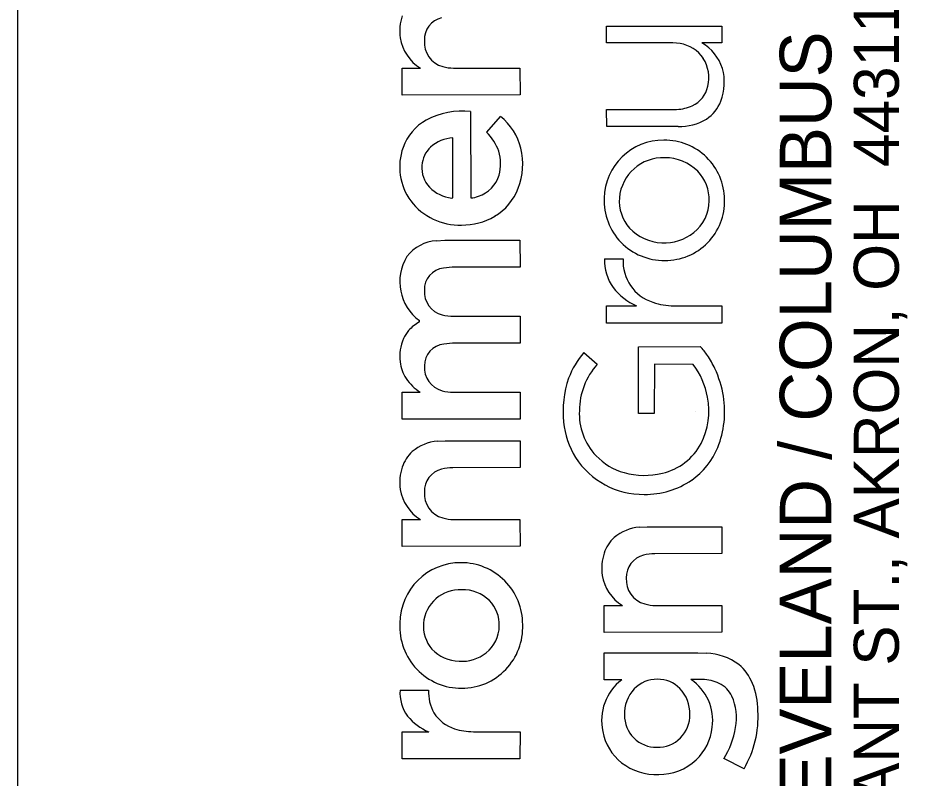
# Model space of a CAD drawing. Extents: x 0 to 34, y 0 to 22.
# Drawn here: x 32 to 32.984, y 3.594 to 4.436 of the extents above; entities that cross this region are included whole.
import ezdxf

# ---------------------------------------------------------------- set-up
doc = ezdxf.new("R2010")
doc.units = 0
doc.layers.add('SH_Border', color=7, linetype='Continuous')
doc.layers.add('SH_Data', color=7, linetype='Continuous')

msp = doc.modelspace()

# ---------------------------------------------------------------- linework, layer by layer
at = {"layer": 'SH_Border'}
msp.add_line((32, 0.5), (32, 21.5), dxfattribs=at)
at = {"layer": 'SH_Data'}
for p, q in [((32.65152, 4.40801), (32.65153, 4.42672)), ((32.65153, 4.42672), (32.7791, 4.42664)), ((32.7791, 4.42664), (32.77908, 4.40796)), ((32.7249, 4.40796), (32.65152, 4.40801)), ((32.7328, 4.40727), (32.7249, 4.40796)), ((32.77908, 4.40796), (32.75689, 4.40796)), ((32.42542, 4.38016), (32.44552, 4.38021)), ((32.42542, 4.35035), (32.42542, 4.38016)), ((32.48222, 4.38021), (32.55569, 4.38021)), ((32.55569, 4.38021), (32.55571, 4.35045)), ((32.55571, 4.35045), (32.42542, 4.35035)), ((32.50108, 4.33209), (32.50118, 4.23657)), ((32.65154, 4.33443), (32.72905, 4.3345)), ((32.65165, 4.31543), (32.65154, 4.33443)), ((32.51882, 4.30927), (32.53422, 4.32662)), ((32.73073, 4.31543), (32.65165, 4.31543)), ((32.48144, 4.23644), (32.48144, 4.30296)), ((32.48016, 4.23628), (32.48144, 4.23644)), ((32.46329, 4.18915), (32.47259, 4.18968)), ((32.47259, 4.18968), (32.55557, 4.18968)), ((32.55557, 4.18968), (32.55571, 4.15982)), ((32.64932, 4.16907), (32.66978, 4.16907)), ((32.48058, 4.15981), (32.47102, 4.15881)), ((32.55571, 4.15982), (32.48058, 4.15981)), ((32.65152, 4.11699), (32.68476, 4.117)), ((32.65152, 4.098), (32.65152, 4.11699)), ((32.72605, 4.11703), (32.7791, 4.11696)), ((32.7791, 4.11696), (32.77903, 4.098)), ((32.48218, 4.10553), (32.55571, 4.10548)), ((32.55571, 4.10548), (32.55571, 4.07568)), ((32.44443, 4.09922), (32.44455, 4.10072)), ((32.77903, 4.098), (32.65152, 4.098)), ((32.4809, 4.07567), (32.47143, 4.07474)), ((32.55571, 4.07568), (32.4809, 4.07567)), ((32.62636, 4.06548), (32.64114, 4.05241)), ((32.6868, 4.07185), (32.75516, 4.07192)), ((32.6868, 3.99778), (32.6868, 4.07185)), ((32.70448, 4.05241), (32.70432, 3.99775)), ((32.74737, 4.05227), (32.70448, 4.05241)), ((32.42542, 3.99152), (32.42545, 4.02138)), ((32.42545, 4.02138), (32.44515, 4.02138)), ((32.48206, 4.02138), (32.55571, 4.02136)), ((32.55571, 4.02136), (32.55571, 3.99156)), ((32.70432, 3.99775), (32.6868, 3.99778)), ((32.75, 4), (32.75, 4)), ((32.55571, 3.99156), (32.42542, 3.99152)), ((32.46439, 3.96736), (32.47289, 3.96783)), ((32.47289, 3.96783), (32.55571, 3.96783)), ((32.55571, 3.96783), (32.55571, 3.93804)), ((32.55571, 3.93804), (32.4814, 3.93796)), ((32.42542, 3.88066), (32.44552, 3.88071)), ((32.42542, 3.85086), (32.42542, 3.88066)), ((32.48222, 3.88071), (32.55569, 3.88071)), ((32.55569, 3.88071), (32.55571, 3.85096)), ((32.68784, 3.8722), (32.69634, 3.87266)), ((32.69634, 3.87266), (32.77916, 3.87266)), ((32.77916, 3.87266), (32.77917, 3.84287)), ((32.55571, 3.85096), (32.42542, 3.85086)), ((32.77917, 3.84287), (32.70485, 3.8428)), ((32.64888, 3.7855), (32.66897, 3.78555)), ((32.64888, 3.75569), (32.64888, 3.7855)), ((32.70568, 3.78555), (32.77915, 3.78555)), ((32.77915, 3.78555), (32.77917, 3.75579)), ((32.77917, 3.75579), (32.64888, 3.75569)), ((32.6489, 3.70336), (32.64889, 3.73322)), ((32.64889, 3.73322), (32.75236, 3.73322)), ((32.75236, 3.73322), (32.76191, 3.73285)), ((32.66836, 3.70336), (32.6489, 3.70336)), ((32.75763, 3.70356), (32.74487, 3.70361)), ((32.42299, 3.69193), (32.45454, 3.69193)), ((32.42542, 3.64577), (32.45473, 3.64579)), ((32.42542, 3.61593), (32.42542, 3.64577)), ((32.50413, 3.64581), (32.55571, 3.64573)), ((32.55571, 3.64573), (32.55565, 3.61593)), ((32.55565, 3.61593), (32.42542, 3.61593)), ((32.8036, 3.60491), (32.7812, 3.61598))]:
    msp.add_line(p, q, dxfattribs=at)
for points in [[(32.7328, 4.40727), (32.7249, 4.40796), (32.65152, 4.40801), (32.65153, 4.42672), (32.7791, 4.42664), (32.77908, 4.40796), (32.75689, 4.40796)], [(32.42542, 4.35035), (32.42542, 4.38016), (32.44552, 4.38021)], [(32.48222, 4.38021), (32.55569, 4.38021), (32.55571, 4.35045), (32.42542, 4.35035)], [(32.50108, 4.33209), (32.50118, 4.23657)], [(32.73073, 4.31543), (32.65165, 4.31543), (32.65154, 4.33443), (32.72905, 4.3345)], [(32.51882, 4.30927), (32.53422, 4.32662)], [(32.48016, 4.23628), (32.48144, 4.23644), (32.48144, 4.30296)], [(32.46329, 4.18915), (32.47259, 4.18968), (32.55557, 4.18968), (32.55571, 4.15982), (32.48058, 4.15981), (32.47102, 4.15881)], [(32.64932, 4.16907), (32.66978, 4.16907)], [(32.72605, 4.11703), (32.7791, 4.11696), (32.77903, 4.098), (32.65152, 4.098)], [(32.65152, 4.098), (32.65152, 4.11699), (32.68476, 4.117)], [(32.48218, 4.10553), (32.55571, 4.10548), (32.55571, 4.07568), (32.4809, 4.07567), (32.47143, 4.07474)], [(32.44443, 4.09922), (32.44455, 4.10072)], [(32.62636, 4.06548), (32.64114, 4.05241)], [(32.74737, 4.05227), (32.70448, 4.05241), (32.70432, 3.99775), (32.6868, 3.99778), (32.6868, 4.07185), (32.75516, 4.07192)], [(32.42542, 3.99152), (32.42545, 4.02138), (32.44515, 4.02138)], [(32.48206, 4.02138), (32.55571, 4.02136), (32.55571, 3.99156), (32.42542, 3.99152)], [(32.46439, 3.96736), (32.47289, 3.96783), (32.55571, 3.96783), (32.55571, 3.93804), (32.4814, 3.93796)], [(32.42542, 3.85086), (32.42542, 3.88066), (32.44552, 3.88071)], [(32.48222, 3.88071), (32.55569, 3.88071), (32.55571, 3.85096), (32.42542, 3.85086)], [(32.68784, 3.8722), (32.69634, 3.87266), (32.77916, 3.87266), (32.77917, 3.84287), (32.70485, 3.8428)], [(32.64888, 3.75569), (32.64888, 3.7855), (32.66897, 3.78555)], [(32.70568, 3.78555), (32.77915, 3.78555), (32.77917, 3.75579), (32.64888, 3.75569)], [(32.66836, 3.70336), (32.6489, 3.70336), (32.64889, 3.73322), (32.75236, 3.73322), (32.76191, 3.73285)], [(32.75763, 3.70356), (32.74487, 3.70361)], [(32.42299, 3.69193), (32.45454, 3.69193)], [(32.50413, 3.64581), (32.55571, 3.64573), (32.55565, 3.61593), (32.42542, 3.61593)], [(32.42542, 3.61593), (32.42542, 3.64577), (32.45473, 3.64579)], [(32.8036, 3.60491), (32.7812, 3.61598)]]:
    msp.add_lwpolyline(points, dxfattribs=at)
for centre, radius, start, end in [((32.47872, 4.42108), 0.05602, 162.27398, 187.79173), ((32.47872, 4.42108), 0.05602, 162.27398, 187.79173), ((32.47482, 4.41155), 0.02498, 103.68683, 182.21395), ((32.47482, 4.41155), 0.02498, 103.68683, 182.21395), ((32.47027, 4.4209), 0.04763, 188.96462, 238.69865), ((32.47027, 4.4209), 0.04763, 188.96462, 238.69865), ((32.47735, 4.40846), 0.02757, 175.58441, 255.13816), ((32.47735, 4.40846), 0.02757, 175.58441, 255.13816), ((32.72711, 4.36998), 0.03772, 33.50082, 81.32954), ((32.72711, 4.36998), 0.03772, 33.50082, 81.32954), ((32.73239, 4.36485), 0.04959, 17.62209, 60.38974), ((32.73239, 4.36485), 0.04959, 17.62209, 60.38974), ((32.72414, 4.3695), 0.04048, 346.56179, 31.75389), ((32.72414, 4.3695), 0.04048, 346.56179, 31.75389), ((32.48183, 4.42235), 0.04215, 254.08913, 270.52838), ((32.48183, 4.42235), 0.04215, 254.08913, 270.52838), ((32.72343, 4.36415), 0.05838, 339.16197, 15.61485), ((32.72343, 4.36415), 0.05838, 339.16197, 15.61485), ((32.73371, 4.36616), 0.03042, 294.63214, 348.48625), ((32.73371, 4.36616), 0.03042, 294.63214, 348.48625), ((32.739, 4.35901), 0.04201, 303.10391, 338.15613), ((32.739, 4.35901), 0.04201, 303.10391, 338.15613), ((32.49176, 4.24874), 0.08387, 83.62118, 118.28448), ((32.49176, 4.24874), 0.08387, 83.62118, 118.28448), ((32.72747, 4.38081), 0.04633, 271.95199, 294.08943), ((32.72747, 4.38081), 0.04633, 271.95199, 294.08943), ((32.47894, 4.27368), 0.05583, 118.82935, 160.62242), ((32.47894, 4.27368), 0.05583, 118.82935, 160.62242), ((32.49399, 4.2763), 0.06443, 13.53275, 51.36266), ((32.49399, 4.2763), 0.06443, 13.53275, 51.36266), ((32.7321, 4.37256), 0.05715, 268.62699, 301.47779), ((32.7321, 4.37256), 0.05715, 268.62699, 301.47779), ((32.4844, 4.26071), 0.04236, 94.01311, 130.88062), ((32.4844, 4.26071), 0.04236, 94.01311, 130.88062), ((32.48033, 4.27018), 0.05485, 19.0387, 45.44322), ((32.48033, 4.27018), 0.05485, 19.0387, 45.44322), ((32.48697, 4.27074), 0.06438, 160.52138, 215.78155), ((32.48697, 4.27074), 0.06438, 160.52138, 215.78155), ((32.47703, 4.2709), 0.02985, 132.98553, 177.1802), ((32.47703, 4.2709), 0.02985, 132.98553, 177.1802), ((32.48289, 4.27384), 0.0758, 339.35431, 13.37708), ((32.48289, 4.27384), 0.0758, 339.35431, 13.37708), ((32.71435, 4.23484), 0.06552, 89.48213, 178.77752), ((32.71435, 4.23484), 0.06552, 89.48213, 178.77752), ((32.71582, 4.23414), 0.06623, 0.42265, 90.7613), ((32.71582, 4.23414), 0.06623, 0.42265, 90.7613), ((32.48724, 4.27433), 0.04701, 344.60723, 17.00675), ((32.48724, 4.27433), 0.04701, 344.60723, 17.00675), ((32.47824, 4.26966), 0.03114, 175.00138, 223.2876), ((32.47824, 4.26966), 0.03114, 175.00138, 223.2876), ((32.71397, 4.23244), 0.04846, 87.68827, 175.01696), ((32.71397, 4.23244), 0.04846, 87.68827, 175.01696), ((32.71659, 4.23036), 0.05052, 44.91202, 90.75914), ((32.71659, 4.23036), 0.05052, 44.91202, 90.75914), ((32.49895, 4.27177), 0.03504, 288.01084, 343.55364), ((32.49895, 4.27177), 0.03504, 288.01084, 343.55364), ((32.71955, 4.23452), 0.04549, 358.32279, 43.83486), ((32.71955, 4.23452), 0.04549, 358.32279, 43.83486), ((32.48546, 4.27826), 0.04232, 225.06454, 262.79701), ((32.48546, 4.27826), 0.04232, 225.06454, 262.79701), ((32.49548, 4.26982), 0.0626, 300.94393, 338.73223), ((32.49548, 4.26982), 0.0626, 300.94393, 338.73223), ((32.48908, 4.27516), 0.06872, 217.74341, 271.65606), ((32.48908, 4.27516), 0.06872, 217.74341, 271.65606), ((32.50129, 4.25678), 0.02021, 269.70042, 294.87295), ((32.50129, 4.25678), 0.02021, 269.70042, 294.87295), ((32.71483, 4.2334), 0.06606, 177.53728, 270.94524), ((32.71483, 4.2334), 0.06606, 177.53728, 270.94524), ((32.71085, 4.23311), 0.0453, 175.51467, 221.42047), ((32.71085, 4.23311), 0.0453, 175.51467, 221.42047), ((32.71671, 4.23271), 0.06536, 269.30834, 1.67905), ((32.71671, 4.23271), 0.06536, 269.30834, 1.67905), ((32.71931, 4.23374), 0.04572, 308.90382, 359.30947), ((32.71931, 4.23374), 0.04572, 308.90382, 359.30947), ((32.49204, 4.27702), 0.07055, 269.20529, 300.33566), ((32.49204, 4.27702), 0.07055, 269.20529, 300.33566), ((32.71399, 4.23734), 0.05046, 222.66255, 268.37331), ((32.71399, 4.23734), 0.05046, 222.66255, 268.37331), ((32.71567, 4.23859), 0.05178, 266.55312, 308.67253), ((32.71567, 4.23859), 0.05178, 266.55312, 308.67253), ((32.46638, 4.14404), 0.04521, 93.91118, 142.30723), ((32.46638, 4.14404), 0.04521, 93.91118, 142.30723), ((32.47585, 4.14373), 0.05319, 148.28793, 233.9556), ((32.47585, 4.14373), 0.05319, 148.28793, 233.9556), ((32.69878, 4.16662), 0.04952, 177.16211, 216.28024), ((32.69878, 4.16662), 0.04952, 177.16211, 216.28024), ((32.71735, 4.16638), 0.04764, 176.76988, 252.15044), ((32.71735, 4.16638), 0.04764, 176.76988, 252.15044), ((32.47384, 4.13499), 0.02399, 96.75763, 181.6251), ((32.47384, 4.13499), 0.02399, 96.75763, 181.6251), ((32.47577, 4.13241), 0.02597, 175.81573, 256.16716), ((32.47577, 4.13241), 0.02597, 175.81573, 256.16716), ((32.70975, 4.17555), 0.06366, 216.91526, 246.88619), ((32.70975, 4.17555), 0.06366, 216.91526, 246.88619), ((32.7269, 4.19175), 0.07473, 251.13884, 269.34694), ((32.7269, 4.19175), 0.07473, 251.13884, 269.34694), ((32.4817, 4.15053), 0.04501, 254.34629, 270.61033), ((32.4817, 4.15053), 0.04501, 254.34629, 270.61033), ((32.4638, 4.06267), 0.04137, 117.91625, 139.24296), ((32.4638, 4.06267), 0.04137, 117.91625, 139.24296), ((32.46194, 4.06452), 0.03875, 139.52447, 154.84698), ((32.46194, 4.06452), 0.03875, 139.52447, 154.84698), ((32.47144, 4.0612), 0.04877, 156.06382, 187.3493), ((32.47144, 4.0612), 0.04877, 156.06382, 187.3493), ((32.47421, 4.05056), 0.02434, 96.5532, 179.94902), ((32.47421, 4.05056), 0.02434, 96.5532, 179.94902), ((32.70163, 4.00187), 0.09855, 139.79476, 159.13696), ((32.70163, 4.00187), 0.09855, 139.79476, 159.13696), ((32.72498, 4.03937), 0.04438, 30.98913, 47.16099), ((32.72498, 4.03937), 0.04438, 30.98913, 47.16099), ((32.46461, 4.05974), 0.04181, 186.5579, 213.38846), ((32.46461, 4.05974), 0.04181, 186.5579, 213.38846), ((32.67091, 4.00018), 0.11106, 25.30315, 33.96179), ((32.67091, 4.00018), 0.11106, 25.30315, 33.96179), ((32.47608, 4.04863), 0.02628, 175.722, 255.78627), ((32.47608, 4.04863), 0.02628, 175.722, 255.78627), ((32.69899, 4.00079), 0.07753, 138.25804, 179.70064), ((32.69899, 4.00079), 0.07753, 138.25804, 179.70064), ((32.67889, 4.00099), 0.08556, 10.07509, 36.83189), ((32.67889, 4.00099), 0.08556, 10.07509, 36.83189), ((32.6704, 3.99987), 0.11166, 8.80339, 25.33484), ((32.6704, 3.99987), 0.11166, 8.80339, 25.33484), ((32.47886, 4.07078), 0.0598, 214.70433, 235.68724), ((32.47886, 4.07078), 0.0598, 214.70433, 235.68724), ((32.7187, 3.99968), 0.11536, 161.14379, 185.62812), ((32.7187, 3.99968), 0.11536, 161.14379, 185.62812), ((32.48195, 4.06518), 0.0438, 253.66719, 270.14979), ((32.48195, 4.06518), 0.0438, 253.66719, 270.14979), ((32.68425, 4.00057), 0.08036, 333.46689, 11.03668), ((32.68425, 4.00057), 0.08036, 333.46689, 11.03668), ((32.67564, 3.99977), 0.10649, 338.28866, 9.28548), ((32.67564, 3.99977), 0.10649, 338.28866, 9.28548), ((32.68811, 3.99732), 0.06676, 176.66577, 223.6912), ((32.68811, 3.99732), 0.06676, 176.66577, 223.6912), ((32.69336, 3.99699), 0.08987, 185.50773, 212.01294), ((32.69336, 3.99699), 0.08987, 185.50773, 212.01294), ((32.46871, 3.91767), 0.04988, 94.97056, 130.22484), ((32.46871, 3.91767), 0.04988, 94.97056, 130.22484), ((32.69868, 3.99547), 0.0652, 282.88151, 331.81475), ((32.69868, 3.99547), 0.0652, 282.88151, 331.81475), ((32.69835, 3.99168), 0.08241, 305.03061, 337.67573), ((32.69835, 3.99168), 0.08241, 305.03061, 337.67573), ((32.46348, 3.92602), 0.04016, 132.22383, 161.68229), ((32.46348, 3.92602), 0.04016, 132.22383, 161.68229), ((32.69211, 3.99748), 0.08908, 212.70222, 270.71399), ((32.69211, 3.99748), 0.08908, 212.70222, 270.71399), ((32.69045, 4.00011), 0.07039, 224.02147, 253.88), ((32.69045, 4.00011), 0.07039, 224.02147, 253.88), ((32.47872, 3.92158), 0.05602, 162.27398, 187.79173), ((32.47872, 3.92158), 0.05602, 162.27398, 187.79173), ((32.48108, 3.89196), 0.04601, 89.60515, 105.33026), ((32.48108, 3.89196), 0.04601, 89.60515, 105.33026), ((32.47482, 3.91206), 0.02498, 103.68683, 182.21395), ((32.47482, 3.91206), 0.02498, 103.68683, 182.21395), ((32.69318, 4.01254), 0.08309, 254.45353, 283.9512), ((32.69318, 4.01254), 0.08309, 254.45353, 283.9512), ((32.69429, 3.99979), 0.09138, 269.3273, 304.19632), ((32.69429, 3.99979), 0.09138, 269.3273, 304.19632), ((32.47027, 3.92141), 0.04763, 188.96462, 238.69865), ((32.47027, 3.92141), 0.04763, 188.96462, 238.69865), ((32.47735, 3.90897), 0.02757, 175.58441, 255.13816), ((32.47735, 3.90897), 0.02757, 175.58441, 255.13816), ((32.48183, 3.92286), 0.04215, 254.08913, 270.52838), ((32.48183, 3.92286), 0.04215, 254.08913, 270.52838), ((32.69216, 3.82251), 0.04988, 94.97056, 130.22484), ((32.69216, 3.82251), 0.04988, 94.97056, 130.22484), ((32.68694, 3.83085), 0.04016, 132.22383, 161.68229), ((32.68694, 3.83085), 0.04016, 132.22383, 161.68229), ((32.70217, 3.82642), 0.05602, 162.27398, 187.79173), ((32.70217, 3.82642), 0.05602, 162.27398, 187.79173), ((32.69828, 3.81689), 0.02498, 103.68683, 182.21395), ((32.69828, 3.81689), 0.02498, 103.68683, 182.21395), ((32.70453, 3.79679), 0.04601, 89.60515, 105.33026), ((32.70453, 3.79679), 0.04601, 89.60515, 105.33026), ((32.49014, 3.76543), 0.0674, 89.84756, 179.64047), ((32.49014, 3.76543), 0.0674, 89.84756, 179.64047), ((32.49057, 3.76474), 0.0681, 359.54009, 90.21138), ((32.49057, 3.76474), 0.0681, 359.54009, 90.21138), ((32.69372, 3.82624), 0.04763, 188.96462, 238.69865), ((32.69372, 3.82624), 0.04763, 188.96462, 238.69865), ((32.7008, 3.81381), 0.02757, 175.58441, 255.13816), ((32.7008, 3.81381), 0.02757, 175.58441, 255.13816), ((32.48923, 3.76263), 0.0404, 87.04809, 175.57259), ((32.48923, 3.76263), 0.0404, 87.04809, 175.57259), ((32.49204, 3.75999), 0.04299, 45.84264, 90.98008), ((32.49204, 3.75999), 0.04299, 45.84264, 90.98008), ((32.49458, 3.76421), 0.03821, 357.88569, 44.15902), ((32.49458, 3.76421), 0.03821, 357.88569, 44.15902), ((32.70529, 3.82769), 0.04215, 254.08913, 270.52838), ((32.70529, 3.82769), 0.04215, 254.08913, 270.52838), ((32.49083, 3.76209), 0.06819, 176.8344, 270.40384), ((32.49083, 3.76209), 0.06819, 176.8344, 270.40384), ((32.48729, 3.7625), 0.03848, 175.15378, 221.14706), ((32.48729, 3.7625), 0.03848, 175.15378, 221.14706), ((32.49123, 3.76139), 0.06749, 270.06243, 2.37759), ((32.49123, 3.76139), 0.06749, 270.06243, 2.37759), ((32.49446, 3.76318), 0.0383, 308.28936, 359.43468), ((32.49446, 3.76318), 0.0383, 308.28936, 359.43468), ((32.48919, 3.76607), 0.04228, 223.09994, 268.80895), ((32.48919, 3.76607), 0.04228, 223.09994, 268.80895), ((32.49096, 3.7679), 0.04418, 266.56515, 308.06078), ((32.49096, 3.7679), 0.04418, 266.56515, 308.06078), ((32.75907, 3.66789), 0.06503, 53.40344, 87.49062), ((32.75907, 3.66789), 0.06503, 53.40344, 87.49062), ((32.76517, 3.68039), 0.05141, 21.60748, 50.5577), ((32.76517, 3.68039), 0.05141, 21.60748, 50.5577), ((32.70292, 3.65813), 0.05692, 127.37482, 192.22468), ((32.70292, 3.65813), 0.05692, 127.37482, 192.22468), ((32.70693, 3.66927), 0.0346, 88.47302, 136.42562), ((32.70693, 3.66927), 0.0346, 88.47302, 136.42562), ((32.70814, 3.66963), 0.03424, 44.27195, 90.47623), ((32.70814, 3.66963), 0.03424, 44.27195, 90.47623), ((32.71421, 3.65829), 0.05472, 352.1125, 55.92295), ((32.71421, 3.65829), 0.05472, 352.1125, 55.92295), ((32.75666, 3.65725), 0.04633, 65.01687, 88.8011), ((32.75666, 3.65725), 0.04633, 65.01687, 88.8011), ((32.46616, 3.68882), 0.04329, 175.87313, 216.34747), ((32.46616, 3.68882), 0.04329, 175.87313, 216.34747), ((32.50087, 3.68948), 0.04639, 176.9688, 209.60636), ((32.50087, 3.68948), 0.04639, 176.9688, 209.60636), ((32.71141, 3.66602), 0.0401, 137.46739, 182.33237), ((32.71141, 3.66602), 0.0401, 137.46739, 182.33237), ((32.70368, 3.666), 0.03996, 358.57141, 43.53765), ((32.70368, 3.666), 0.03996, 358.57141, 43.53765), ((32.7626, 3.67155), 0.03085, 26.26808, 63.80301), ((32.7626, 3.67155), 0.03085, 26.26808, 63.80301), ((32.73069, 3.66714), 0.08835, 1.15143, 21.3627), ((32.73069, 3.66714), 0.08835, 1.15143, 21.3627), ((32.73565, 3.66154), 0.05953, 349.30734, 23.43071), ((32.73565, 3.66154), 0.05953, 349.30734, 23.43071), ((32.47466, 3.69716), 0.05511, 218.09809, 248.7907), ((32.47466, 3.69716), 0.05511, 218.09809, 248.7907), ((32.49514, 3.68814), 0.04079, 211.94466, 253.2028), ((32.49514, 3.68814), 0.04079, 211.94466, 253.2028), ((32.70645, 3.6637), 0.03511, 178.88208, 271.08374), ((32.70645, 3.6637), 0.03511, 178.88208, 271.08374), ((32.70818, 3.66404), 0.03546, 268.27882, 1.55016), ((32.70818, 3.66404), 0.03546, 268.27882, 1.55016), ((32.70538, 3.66244), 0.11383, 329.6388, 3.25998), ((32.70538, 3.66244), 0.11383, 329.6388, 3.25998), ((32.50465, 3.7165), 0.07069, 252.46555, 269.57296), ((32.50465, 3.7165), 0.07069, 252.46555, 269.57296), ((32.70463, 3.65696), 0.05837, 190.75182, 231.28919), ((32.70463, 3.65696), 0.05837, 190.75182, 231.28919), ((32.70988, 3.65708), 0.05887, 313.74196, 353.8554), ((32.70988, 3.65708), 0.05887, 313.74196, 353.8554), ((32.70738, 3.66334), 0.08771, 327.31495, 351.57478), ((32.70738, 3.66334), 0.08771, 327.31495, 351.57478), ((32.70954, 3.65901), 0.06051, 269.6361, 312.70877), ((32.70954, 3.65901), 0.06051, 269.6361, 312.70877), ((32.70632, 3.66112), 0.06269, 232.46061, 272.59022), ((32.70632, 3.66112), 0.06269, 232.46061, 272.59022)]:
    msp.add_arc(centre, radius, start, end, dxfattribs=at)

# ---------------------------------------------------------------- texts
for s, height, p in [('450 GRANT ST., AKRON, OH  44311', 0.0498462, (32.97489, 3.33738)), ('AKRON / CLEVELAND / COLUMBUS', 0.056969, (32.90012, 3.138))]:
    msp.add_text(s, height=height, rotation=90, dxfattribs=at).set_placement(p)

doc.saveas('drawing.dxf')
